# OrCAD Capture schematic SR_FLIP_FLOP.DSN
size A
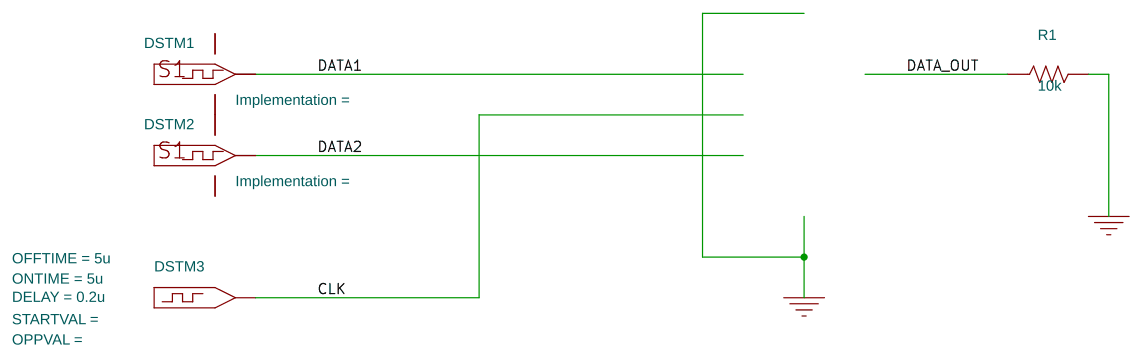
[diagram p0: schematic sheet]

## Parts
DSTM1  DigStim1
DSTM2  DigStim1
DSTM3  DigitalPulse_app
R1  10k  [AXRC05]

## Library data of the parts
DSTM1 DSTM2 = DigStim1
DSTM3 = DigitalPulse_app: AppProp: OFFTIME=5u,ONTIME=5u,DELAY=0,ROUT=10,VOH=5,VOL=0; DELAY: 0.2u; OFFTIME: 5u; ONTIME: 5u
R1 = R

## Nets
GND: DSTM1.3(GND) DSTM2.3(GND)
VCC: DSTM1.2(VCC) DSTM2.2(VCC)
0: R1.2
CLK: DSTM3.1
DATA1: DSTM1.OUT
DATA2: DSTM2.OUT
DATA_OUT: R1.1
